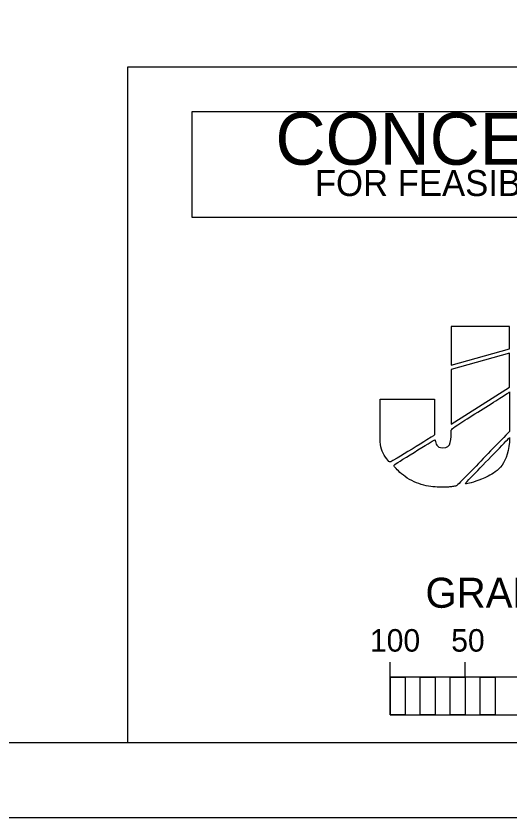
# Model space of a CAD drawing. Extents: x 1636954 to 1644154, y 841334 to 845582.
# Drawn here: x 1642730 to 1643059, y 841334 to 841868 of the extents above; entities that cross this region are included whole.
import ezdxf

# ---------------------------------------------------------------- set-up
doc = ezdxf.new("R2010")
doc.units = 0
for name, color, linetype in [('Default', 7, 'Continuous'), ('Scratch_Level_1', 7, 'Continuous'), ('Sheet Data Field CELL', 7, 'Continuous'), ('Sheet Plan And Profile CELL', 7, 'Continuous'), ('Sheet Sticker Incomplete CELL', 7, 'Continuous'), ('Sheet Title CELL', 7, 'Continuous')]:
    doc.layers.add(name, color=color, linetype=linetype)

msp = doc.modelspace()

# ---------------------------------------------------------------- linework, layer by layer
at = {"layer": 'Default'}
for p, q in [((1643058.8, 841661.36), (1643019.84, 841661.36)), ((1643019.84, 841661.36), (1643019.84, 841635.52)), ((1643058.8, 841661.36), (1643019.84, 841661.36)), ((1643019.84, 841661.36), (1643019.84, 841635.52)), ((1643058.8, 841646.32), (1643058.8, 841661.36)), ((1643058.8, 841646.32), (1643058.8, 841661.36)), ((1643019.84, 841635.52), (1643058.8, 841646.32)), ((1643019.84, 841635.52), (1643058.8, 841646.32)), ((1643058.8, 841643.49), (1643019.84, 841632.56)), ((1643058.8, 841643.49), (1643019.84, 841632.56)), ((1643058.8, 841620.92), (1643058.8, 841643.49)), ((1643058.8, 841620.92), (1643058.8, 841643.49)), ((1643019.84, 841632.56), (1643019.84, 841596.24)), ((1643019.84, 841632.56), (1643019.84, 841596.24)), ((1643019.84, 841596.24), (1643058.8, 841620.92)), ((1643019.84, 841596.24), (1643058.8, 841620.92))]:
    msp.add_line(p, q, dxfattribs=at)
for points in [[(1643019.84, 841635.52), (1643058.8, 841646.32), (1643058.8, 841661.36), (1643019.84, 841661.36), (1643019.84, 841635.52)], [(1643019.84, 841635.52), (1643058.8, 841646.32), (1643058.8, 841661.36), (1643019.84, 841661.36), (1643019.84, 841635.52)], [(1643019.84, 841596.24), (1643058.8, 841620.92), (1643058.8, 841643.49), (1643019.84, 841632.56), (1643019.84, 841596.24)], [(1643019.84, 841596.24), (1643058.8, 841620.92), (1643058.8, 841643.49), (1643019.84, 841632.56), (1643019.84, 841596.24)]]:
    msp.add_lwpolyline(points, dxfattribs=at)
for points in [[(1643008.66, 841612.95), (1643008.66, 841612.95), (1642972.59, 841612.95), (1642972.59, 841612.95), (1642972.59, 841612.95), (1642972.59, 841590.39), (1642972.59, 841590.39), (1642972.59, 841590.39), (1642972.59, 841588.01), (1642972.59, 841588.01), (1642972.6, 841580.94), (1642974.91, 841575.35), (1642979.02, 841570.66), (1642979.02, 841570.66), (1643008.66, 841588.66), (1643008.66, 841589.1), (1643008.66, 841589.1), (1643008.66, 841612.95), (1643008.66, 841612.95)], [(1643008.66, 841612.95), (1643008.66, 841612.95), (1642972.59, 841612.95), (1642972.59, 841612.95), (1642972.59, 841612.95), (1642972.59, 841590.39), (1642972.59, 841590.39), (1642972.59, 841590.39), (1642972.59, 841588.01), (1642972.59, 841588.01), (1642972.6, 841580.94), (1642974.91, 841575.35), (1642979.02, 841570.66), (1642979.02, 841570.66), (1643008.66, 841588.66), (1643008.66, 841589.1), (1643008.66, 841589.1), (1643008.66, 841612.95), (1643008.66, 841612.95)], [(1643008.66, 841612.95), (1643008.66, 841612.95), (1642972.59, 841612.95), (1642972.59, 841612.95), (1642972.59, 841612.95), (1642972.59, 841590.39), (1642972.59, 841590.39), (1642972.59, 841590.39), (1642972.59, 841588.01), (1642972.59, 841588.01), (1642972.6, 841580.94), (1642974.91, 841575.35), (1642979.02, 841570.66), (1642979.02, 841570.66), (1643008.66, 841588.66), (1643008.66, 841589.1), (1643008.66, 841589.1), (1643008.66, 841612.95), (1643008.66, 841612.95)], [(1643008.66, 841612.95), (1643008.66, 841612.95), (1642972.59, 841612.95), (1642972.59, 841612.95), (1642972.59, 841612.95), (1642972.59, 841590.39), (1642972.59, 841590.39), (1642972.59, 841590.39), (1642972.59, 841588.01), (1642972.59, 841588.01), (1642972.6, 841580.94), (1642974.91, 841575.35), (1642979.02, 841570.66), (1642979.02, 841570.66), (1643008.66, 841588.66), (1643008.66, 841589.1), (1643008.66, 841589.1), (1643008.66, 841612.95), (1643008.66, 841612.95)], [(1643014.25, 841580.49), (1643011.94, 841580.49), (1643009.94, 841581.78), (1643009.11, 841586.08), (1643009.11, 841586.08), (1642981.14, 841568.79), (1642981.14, 841568.79), (1642989.76, 841559.73), (1643003.51, 841554.33), (1643015.15, 841554.33), (1643018.17, 841554.33), (1643020.49, 841554.59), (1643023.7, 841555.23), (1643023.7, 841555.23), (1643058.8, 841591.48), (1643058.8, 841591.48), (1643058.8, 841591.48), (1643058.8, 841617.71), (1643058.8, 841617.71), (1643058.8, 841617.71), (1643019.84, 841592.96), (1643019.84, 841592.96), (1643019.84, 841583.13), (1643017.46, 841580.49), (1643014.25, 841580.49)], [(1643014.25, 841580.49), (1643011.94, 841580.49), (1643009.94, 841581.78), (1643009.11, 841586.08), (1643009.11, 841586.08), (1642981.14, 841568.79), (1642981.14, 841568.79), (1642989.76, 841559.73), (1643003.51, 841554.33), (1643015.15, 841554.33), (1643018.17, 841554.33), (1643020.49, 841554.59), (1643023.7, 841555.23), (1643023.7, 841555.23), (1643058.8, 841591.48), (1643058.8, 841591.48), (1643058.8, 841591.48), (1643058.8, 841617.71), (1643058.8, 841617.71), (1643058.8, 841617.71), (1643019.84, 841592.96), (1643019.84, 841592.96), (1643019.84, 841583.13), (1643017.46, 841580.49), (1643014.25, 841580.49)], [(1643014.25, 841580.49), (1643011.94, 841580.49), (1643009.94, 841581.78), (1643009.11, 841586.08), (1643009.11, 841586.08), (1642981.14, 841568.79), (1642981.14, 841568.79), (1642989.76, 841559.73), (1643003.51, 841554.33), (1643015.15, 841554.33), (1643018.17, 841554.33), (1643020.49, 841554.59), (1643023.7, 841555.23), (1643023.7, 841555.23), (1643058.8, 841591.48), (1643058.8, 841591.48), (1643058.8, 841591.48), (1643058.8, 841617.71), (1643058.8, 841617.71), (1643058.8, 841617.71), (1643019.84, 841592.96), (1643019.84, 841592.96), (1643019.84, 841583.13), (1643017.46, 841580.49), (1643014.25, 841580.49)], [(1643014.25, 841580.49), (1643011.94, 841580.49), (1643009.94, 841581.78), (1643009.11, 841586.08), (1643009.11, 841586.08), (1642981.14, 841568.79), (1642981.14, 841568.79), (1642989.76, 841559.73), (1643003.51, 841554.33), (1643015.15, 841554.33), (1643018.17, 841554.33), (1643020.49, 841554.59), (1643023.7, 841555.23), (1643023.7, 841555.23), (1643058.8, 841591.48), (1643058.8, 841591.48), (1643058.8, 841591.48), (1643058.8, 841617.71), (1643058.8, 841617.71), (1643058.8, 841617.71), (1643019.84, 841592.96), (1643019.84, 841592.96), (1643019.84, 841583.13), (1643017.46, 841580.49), (1643014.25, 841580.49)], [(1643058.8, 841587.37), (1643058.8, 841587.37), (1643028.46, 841556.06), (1643028.46, 841556.06), (1643043.3, 841559.73), (1643058.09, 841569.56), (1643058.8, 841587.37)], [(1643058.8, 841587.37), (1643058.8, 841587.37), (1643028.46, 841556.06), (1643028.46, 841556.06), (1643043.3, 841559.73), (1643058.09, 841569.56), (1643058.8, 841587.37)], [(1643058.8, 841587.37), (1643058.8, 841587.37), (1643028.46, 841556.06), (1643028.46, 841556.06), (1643043.3, 841559.73), (1643058.09, 841569.56), (1643058.8, 841587.37)], [(1643058.8, 841587.37), (1643058.8, 841587.37), (1643028.46, 841556.06), (1643028.46, 841556.06), (1643043.3, 841559.73), (1643058.09, 841569.56), (1643058.8, 841587.37)]]:
    msp.add_open_spline(points, degree=3, dxfattribs=at)
at = {"layer": 'Scratch_Level_1'}
msp.add_lwpolyline([(1636954.2, 841333.94), (1636954.2, 844733.94), (1644154.2, 844733.94), (1644154.2, 841333.94)], close=True, dxfattribs=at)
at = {"layer": 'Sheet Plan And Profile CELL'}
msp.add_lwpolyline([(1637004.2, 841383.94), (1637004.2, 844683.94), (1644104.2, 844683.94), (1644104.2, 841383.94)], close=True, dxfattribs=at)
msp.add_lwpolyline([(1643454.2, 841383.94), (1643454.2, 841833.94), (1642804.2, 841833.94), (1642804.2, 841383.94)], dxfattribs=at)
at = {"layer": 'Sheet Sticker Incomplete CELL'}
msp.add_lwpolyline([(1642847.4, 841733.94), (1642847.4, 841804.44), (1643411, 841804.44), (1643411, 841733.94)], close=True, dxfattribs=at)
at = {"layer": 'Sheet Title CELL'}
for p, q in [((1642979.2, 841427.72), (1642979.2, 841437.69)), ((1642979.2, 841437.69), (1642979.2, 841437.69)), ((1643029.2, 841427.69), (1643029.2, 841437.72)), ((1642979.2, 841427.72), (1642979.2, 841402.72)), ((1642979.2, 841427.72), (1642979.2, 841427.72)), ((1643279.2, 841427.72), (1642979.2, 841427.72)), ((1642979.2, 841402.72), (1643279.2, 841402.72))]:
    msp.add_line(p, q, dxfattribs=at)
for points in [[(1642979.2, 841427.72), (1642989.2, 841427.72), (1642989.2, 841402.72), (1642979.2, 841402.72)], [(1642999.2, 841427.72), (1643009.2, 841427.72), (1643009.2, 841402.72), (1642999.2, 841402.72)], [(1643019.2, 841427.72), (1643029.2, 841427.72), (1643029.2, 841402.72), (1643019.2, 841402.72)], [(1643039.2, 841427.72), (1643049.2, 841427.72), (1643049.2, 841402.72), (1643039.2, 841402.72)]]:
    msp.add_lwpolyline(points, close=True, dxfattribs=at)

# ---------------------------------------------------------------- texts
at = {"layer": 'Sheet Data Field CELL'}
for s, p in [('100', (1642965.73, 841444.72)), ('50', (1643019.86, 841444.72))]:
    msp.add_text(s, height=15, dxfattribs=at).set_placement(p)
at = {"layer": 'Sheet Sticker Incomplete CELL'}
for s, height, p in [('CONCEPTUAL DRAWING', 34.56, (1642902.82, 841769.04)), ('FOR FEASIBILITY STUDY PURPOSES ONLY', 17.28, (1642929.03, 841748.19))]:
    msp.add_text(s, height=height, dxfattribs=at).set_placement(p)
at = {"layer": 'Sheet Title CELL'}
msp.add_text('GRAPHIC SCALES', height=19.9992, dxfattribs=at).set_placement((1643002.73, 841473.94))

doc.saveas('drawing.dxf')
